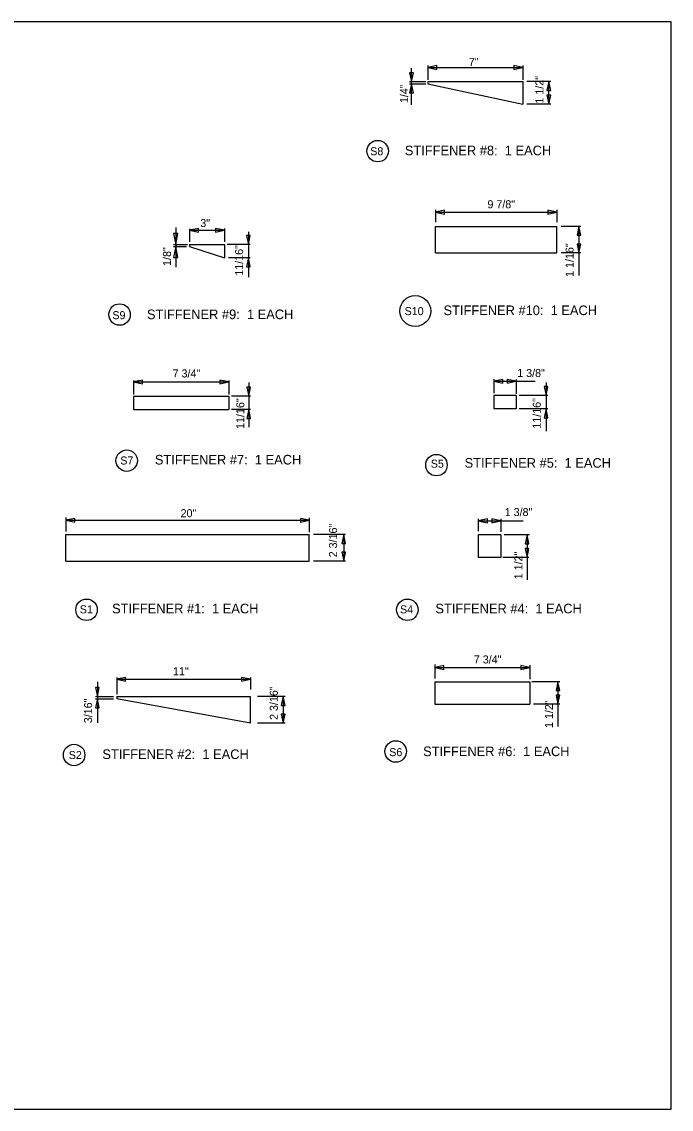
# Model space of a CAD drawing. Extents: x -439.1 to -407.9, y -458.1 to -437.7.
# Drawn here: x -420.02 to -407.86, y -458.05 to -437.68 of the extents above; entities that cross this region are included whole.
import ezdxf

# ---------------------------------------------------------------- set-up
doc = ezdxf.new("R2010")
doc.units = 0
for name, color, linetype in [('Common-Notes', 7, 'Continuous'), ('Draft_Named_Boundary', 7, 'Continuous'), ('Level 4', 7, 'Continuous'), ('Level 45', 7, 'Continuous')]:
    doc.layers.add(name, color=color, linetype=linetype)

msp = doc.modelspace()

# ---------------------------------------------------------------- linework, layer by layer
at = {"layer": 'Draft_Named_Boundary'}
msp.add_lwpolyline([(-439.109, -458.051), (-407.859, -458.051), (-407.859, -437.676), (-439.109, -437.676)], close=True, dxfattribs=at)
at = {"layer": 'Level 4'}
for p, q in [((-412.724, -439.231), (-412.724, -438.543)), ((-412.418, -438.496), (-412.418, -438.765)), ((-412.418, -438.533), (-410.637, -438.533)), ((-410.637, -438.496), (-410.637, -438.765)), ((-412.759, -438.798), (-412.457, -438.798)), ((-412.759, -438.84), (-412.457, -438.84)), ((-412.418, -438.798), (-412.418, -438.84)), ((-412.418, -438.798), (-410.637, -438.798)), ((-412.418, -438.84), (-410.637, -439.218)), ((-410.637, -438.798), (-410.637, -439.218)), ((-410.116, -438.798), (-410.562, -438.798)), ((-410.151, -439.218), (-410.151, -438.798)), ((-410.116, -439.218), (-410.562, -439.218)), ((-412.276, -441.201), (-412.276, -441.429)), ((-412.276, -441.244), (-410.004, -441.244)), ((-410.004, -441.201), (-410.004, -441.429)), ((-412.276, -441.509), (-410.004, -441.509)), ((-412.276, -442.008), (-412.276, -441.509)), ((-410.004, -442.008), (-410.004, -441.509)), ((-409.552, -441.509), (-409.919, -441.509)), ((-409.587, -441.509), (-409.587, -442.428)), ((-417.14, -441.532), (-417.14, -442.272)), ((-416.883, -441.556), (-416.883, -441.798)), ((-416.883, -441.583), (-416.227, -441.583)), ((-416.227, -441.548), (-416.227, -441.802)), ((-415.779, -441.614), (-415.779, -442.461)), ((-417.182, -441.847), (-416.92, -441.847)), ((-417.182, -441.889), (-416.937, -441.889)), ((-416.883, -441.847), (-416.883, -441.889)), ((-416.883, -441.847), (-416.227, -441.847)), ((-416.883, -441.889), (-416.227, -442.099)), ((-416.227, -441.847), (-416.227, -442.099)), ((-415.744, -441.847), (-416.175, -441.847)), ((-415.744, -442.099), (-416.15, -442.099)), ((-412.276, -442.008), (-410.004, -442.008)), ((-409.552, -442.008), (-409.919, -442.008)), ((-411.184, -444.37), (-411.184, -444.634)), ((-417.928, -444.395), (-417.928, -444.66)), ((-417.928, -444.425), (-416.147, -444.425)), ((-416.147, -444.397), (-416.147, -444.662)), ((-415.773, -444.436), (-415.773, -445.27)), ((-411.184, -444.411), (-410.41, -444.411)), ((-410.764, -444.379), (-410.764, -444.644)), ((-410.204, -444.435), (-410.204, -445.347)), ((-417.928, -444.69), (-416.147, -444.69)), ((-417.928, -444.69), (-417.928, -444.941)), ((-416.147, -444.69), (-416.147, -444.941)), ((-415.738, -444.69), (-416.096, -444.69)), ((-410.764, -444.676), (-411.184, -444.676)), ((-411.184, -444.676), (-411.184, -444.927)), ((-410.764, -444.676), (-410.764, -444.927)), ((-410.169, -444.676), (-410.705, -444.676)), ((-417.928, -444.941), (-416.147, -444.941)), ((-415.738, -444.941), (-416.096, -444.941)), ((-410.764, -444.927), (-411.184, -444.927)), ((-410.169, -444.927), (-410.705, -444.927)), ((-419.195, -446.961), (-419.195, -447.225)), ((-419.195, -447.017), (-414.637, -447.017)), ((-414.637, -446.972), (-414.637, -447.236)), ((-411.472, -446.991), (-411.472, -447.222)), ((-411.472, -447.026), (-410.631, -447.026)), ((-411.051, -446.991), (-411.051, -447.233)), ((-419.195, -447.281), (-414.637, -447.281)), ((-419.195, -447.78), (-419.195, -447.281)), ((-414.637, -447.78), (-414.637, -447.281)), ((-413.957, -447.281), (-414.56, -447.281)), ((-413.992, -447.281), (-413.992, -447.78)), ((-411.051, -447.291), (-411.472, -447.291)), ((-411.472, -447.291), (-411.472, -447.711)), ((-411.051, -447.291), (-411.051, -447.711)), ((-410.513, -447.291), (-410.99, -447.291)), ((-410.56, -447.291), (-410.56, -448.131)), ((-419.195, -447.78), (-414.637, -447.78)), ((-413.957, -447.78), (-414.558, -447.78)), ((-411.051, -447.711), (-411.472, -447.711)), ((-410.525, -447.711), (-411.014, -447.711)), ((-412.286, -449.719), (-412.286, -449.983)), ((-412.286, -449.775), (-410.506, -449.775)), ((-410.506, -449.732), (-410.506, -449.996)), ((-418.606, -450.044), (-418.606, -450.814)), ((-418.245, -449.959), (-418.245, -450.274)), ((-418.245, -449.994), (-415.738, -449.994)), ((-415.738, -449.959), (-415.738, -450.185)), ((-412.286, -450.04), (-410.506, -450.04)), ((-412.286, -450.04), (-412.286, -450.46)), ((-410.506, -450.04), (-410.506, -450.46)), ((-409.946, -450.04), (-410.467, -450.04)), ((-409.981, -450.04), (-409.981, -450.88)), ((-418.641, -450.317), (-418.304, -450.317)), ((-418.641, -450.359), (-418.304, -450.359)), ((-418.245, -450.317), (-418.245, -450.359)), ((-418.245, -450.317), (-415.738, -450.317)), ((-415.738, -450.816), (-418.245, -450.359)), ((-415.738, -450.816), (-415.738, -450.317)), ((-415.092, -450.317), (-415.606, -450.317)), ((-415.127, -450.317), (-415.127, -450.816)), ((-412.286, -450.46), (-410.506, -450.46)), ((-409.946, -450.46), (-410.44, -450.46)), ((-415.092, -450.816), (-415.606, -450.816))]:
    msp.add_line(p, q, dxfattribs=at)
for points in [[(-412.759, -438.63), (-412.724, -438.798), (-412.689, -438.63)], [(-412.249, -438.498), (-412.418, -438.533), (-412.249, -438.568)], [(-410.805, -438.568), (-410.637, -438.533), (-410.805, -438.498)], [(-412.689, -439.008), (-412.724, -438.84), (-412.759, -439.008)], [(-410.116, -438.966), (-410.151, -438.798), (-410.186, -438.966)], [(-410.186, -439.05), (-410.151, -439.218), (-410.116, -439.05)], [(-412.108, -441.209), (-412.276, -441.244), (-412.108, -441.279)], [(-410.173, -441.279), (-410.004, -441.244), (-410.173, -441.209)], [(-409.552, -441.677), (-409.587, -441.509), (-409.622, -441.677)], [(-417.182, -441.646), (-417.14, -441.847), (-417.098, -441.646)], [(-416.715, -441.548), (-416.883, -441.583), (-416.715, -441.618)], [(-416.395, -441.618), (-416.227, -441.583), (-416.395, -441.548)], [(-415.814, -441.679), (-415.779, -441.847), (-415.744, -441.679)], [(-417.098, -442.091), (-417.14, -441.889), (-417.182, -442.091)], [(-409.622, -441.84), (-409.587, -442.008), (-409.552, -441.84)], [(-415.744, -442.267), (-415.779, -442.099), (-415.814, -442.267)], [(-411.016, -444.376), (-411.184, -444.411), (-411.016, -444.446)], [(-410.932, -444.446), (-410.764, -444.411), (-410.932, -444.376)], [(-417.759, -444.39), (-417.928, -444.425), (-417.759, -444.46)], [(-416.315, -444.46), (-416.147, -444.425), (-416.315, -444.39)], [(-415.808, -444.521), (-415.773, -444.69), (-415.738, -444.521)], [(-410.239, -444.507), (-410.204, -444.676), (-410.169, -444.507)], [(-415.738, -445.109), (-415.773, -444.941), (-415.808, -445.109)], [(-410.169, -445.095), (-410.204, -444.927), (-410.239, -445.095)], [(-419.027, -446.982), (-419.195, -447.017), (-419.027, -447.052)], [(-414.805, -447.052), (-414.637, -447.017), (-414.805, -446.982)], [(-411.303, -446.991), (-411.472, -447.026), (-411.303, -447.061)], [(-411.219, -447.061), (-411.051, -447.026), (-411.219, -446.991)], [(-413.957, -447.449), (-413.992, -447.281), (-414.027, -447.449)], [(-410.525, -447.459), (-410.56, -447.291), (-410.595, -447.459)], [(-414.027, -447.612), (-413.992, -447.78), (-413.957, -447.612)], [(-410.595, -447.543), (-410.56, -447.711), (-410.525, -447.543)], [(-412.118, -449.74), (-412.286, -449.775), (-412.118, -449.81)], [(-410.674, -449.81), (-410.506, -449.775), (-410.674, -449.74)], [(-418.077, -449.959), (-418.245, -449.994), (-418.077, -450.029)], [(-415.907, -450.029), (-415.738, -449.994), (-415.907, -449.959)], [(-409.946, -450.208), (-409.981, -450.04), (-410.016, -450.208)], [(-418.641, -450.149), (-418.606, -450.317), (-418.571, -450.149)], [(-418.571, -450.527), (-418.606, -450.359), (-418.641, -450.527)], [(-415.092, -450.485), (-415.127, -450.317), (-415.162, -450.485)], [(-410.016, -450.292), (-409.981, -450.46), (-409.946, -450.292)], [(-415.162, -450.648), (-415.127, -450.816), (-415.092, -450.648)]]:
    msp.add_lwpolyline(points, close=True, dxfattribs=at)
for centre, radius in [((-413.357, -440.1), 0.201), ((-412.653, -443.096), 0.289), ((-418.191, -443.161), 0.201), ((-418.057, -445.899), 0.201), ((-412.256, -445.983), 0.201), ((-418.81, -448.693), 0.201), ((-412.801, -448.693), 0.201), ((-419.042, -451.413), 0.201), ((-413.019, -451.348), 0.201)]:
    msp.add_circle(centre, radius, dxfattribs=at)

# ---------------------------------------------------------------- texts
at = {"layer": 'Common-Notes'}
for s, p in [('STIFFENER #8:  1 EACH', (-412.849, -440.177)), ('STIFFENER #9:  1 EACH', (-417.678, -443.248)), ('STIFFENER #10:  1 EACH', (-412.124, -443.172)), ('STIFFENER #7:  1 EACH', (-417.53, -445.971)), ('STIFFENER #5:  1 EACH', (-411.729, -446.031)), ('STIFFENER #1:  1 EACH', (-418.332, -448.76)), ('STIFFENER #4:  1 EACH', (-412.276, -448.76)), ('STIFFENER #2:  1 EACH', (-418.513, -451.489)), ('STIFFENER #6:  1 EACH', (-412.506, -451.435))]:
    msp.add_text(s, height=0.18, dxfattribs=at).set_placement(p)
at = {"layer": 'Level 4'}
for s, p in [('S8', (-413.497, -440.177)), ('S9', (-418.326, -443.248)), ('S10', (-412.853, -443.172)), ('S7', (-418.178, -445.971)), ('S5', (-412.363, -446.031)), ('S1', (-418.936, -448.76)), ('S4', (-412.939, -448.76)), ('S6', (-413.141, -451.435)), ('S2', (-419.143, -451.489))]:
    msp.add_text(s, height=0.15, dxfattribs=at).set_placement(p)
at = {"layer": 'Level 45'}
for s, p in [('7"', (-411.651, -438.504)), ('9 7/8"', (-411.301, -441.17)), ('3"', (-416.679, -441.522)), ('1 3/8"', (-410.744, -444.332)), ('7 3/4"', (-417.198, -444.34)), ('20"', (-417.048, -446.958)), ('1 3/8"', (-410.978, -446.937)), ('7 3/4"', (-411.556, -449.698)), ('11"', (-417.19, -449.92))]:
    msp.add_text(s, height=0.15, dxfattribs=at).set_placement(p)
for s, p in [('1/4"', (-412.787, -439.2)), ('1 1/2"', (-410.252, -439.21)), ('1/8"', (-417.228, -442.25)), ('11/16"', (-415.877, -442.434)), ('1 1/16"', (-409.688, -442.456)), ('11/16"', (-415.855, -445.304)), ('11/16"', (-410.302, -445.3)), ('2 3/16"', (-414.118, -447.71)), ('1 1/2"', (-410.646, -448.121)), ('2 3/16"', (-415.227, -450.757)), ('3/16"', (-418.706, -450.818)), ('1 1/2"', (-410.074, -450.908))]:
    msp.add_text(s, height=0.15, rotation=90, dxfattribs=at).set_placement(p)

doc.saveas('drawing.dxf')
